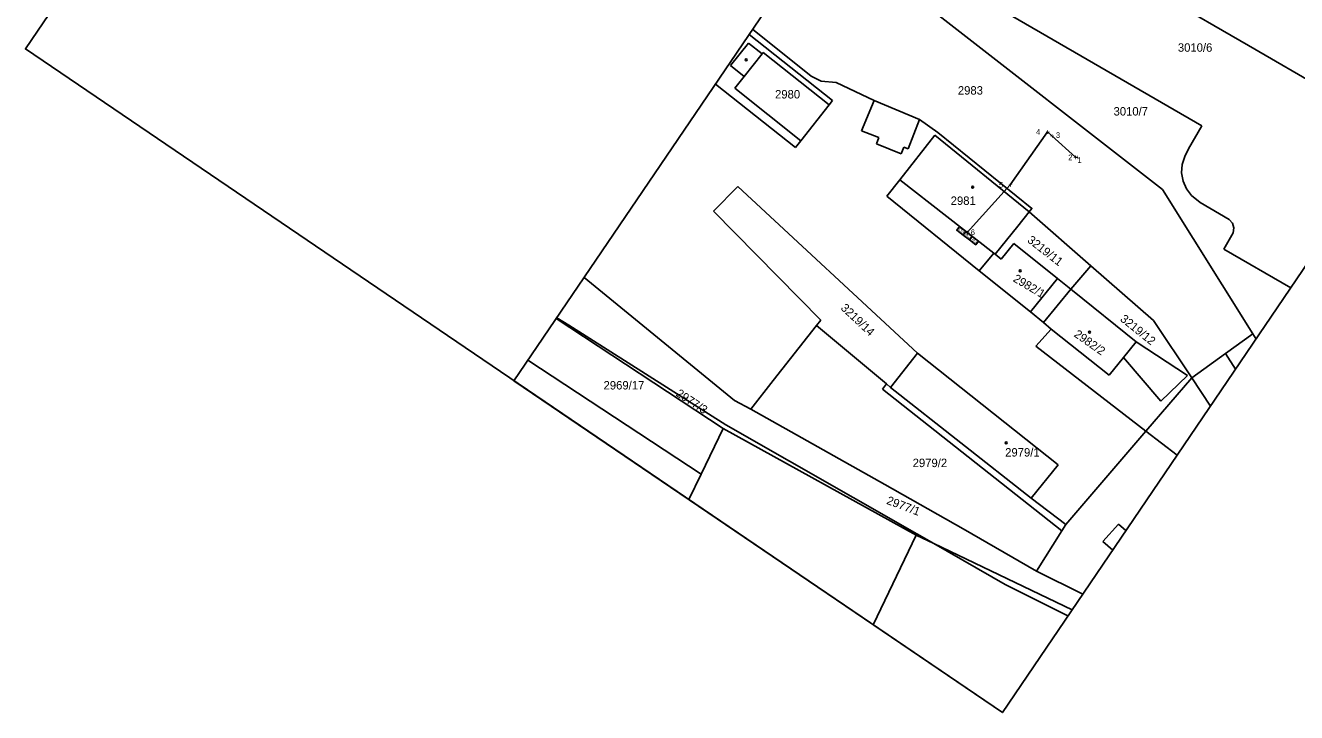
# Model space of a CAD drawing. Extents: x -620405 to -620064, y -1122795 to -1122431.
# Drawn here: x -620404.7 to -620178.7, y -1122795 to -1122672.8 of the extents above; entities that cross this region are included whole.
import ezdxf

# ---------------------------------------------------------------- set-up
doc = ezdxf.new("R2010")
doc.units = 0
for name, color, linetype in [('060602_NAPÁJENÍ_NN', 7, 'Continuous'), ('BODY', 7, 'Continuous'), ('BODY POPIS', 7, 'Continuous'), ('RÁMY', 7, 'Continuous'), ('Vrstva 53', 7, 'Continuous'), ('Vrstva 55', 7, 'Continuous'), ('Vrstva 56', 7, 'Continuous'), ('Vrstva 57', 7, 'Continuous')]:
    doc.layers.add(name, color=color, linetype=linetype)

msp = doc.modelspace()

# ---------------------------------------------------------------- linework, layer by layer
at = {"layer": '060602_NAPÁJENÍ_NN'}
msp.add_lwpolyline([(-620217.64, -1122696.26), (-620218.03, -1122696.24), (-620222.2, -1122692.45), (-620223, -1122691.74), (-620229.59, -1122701.13), (-620237.27, -1122709.63)], dxfattribs=at)
for points in [[(-620238.65, -1122708.58), (-620237.51, -1122709.45), (-620237.99, -1122710.08), (-620239.13, -1122709.21)], [(-620237.51, -1122709.45), (-620236.38, -1122710.32), (-620236.86, -1122710.94), (-620237.99, -1122710.08)], [(-620236.38, -1122710.32), (-620235.25, -1122711.18), (-620235.73, -1122711.81), (-620236.86, -1122710.94)]]:
    msp.add_lwpolyline(points, close=True, dxfattribs=at)
at = {"layer": 'RÁMY'}
for points in [[(-620321.29, -1122554.15), (-620147.57, -1122672.13), (-620231, -1122794.98), (-620404.73, -1122676.99)], [(-620234.43, -1122613.14), (-620147.57, -1122672.13), (-620231, -1122794.98), (-620317.86, -1122735.99)]]:
    msp.add_lwpolyline(points, close=True, dxfattribs=at)
at = {"layer": 'Vrstva 53'}
for p, q in [((-620276.05, -1122674.41), (-620261.22, -1122686.17)), ((-620275.41, -1122673.47), (-620265, -1122681.82)), ((-620265, -1122681.82), (-620263.22, -1122682.69)), ((-620267.81, -1122694.49), (-620282.04, -1122683.25)), ((-620263.22, -1122682.69), (-620260.55, -1122682.94)), ((-620260.55, -1122682.94), (-620253.83, -1122686.12)), ((-620261.82, -1122686.93), (-620261.22, -1122686.17)), ((-620253.83, -1122686.12), (-620245.73, -1122689.53)), ((-620261.82, -1122686.93), (-620266.86, -1122693.31)), ((-620245.73, -1122689.53), (-620242.51, -1122691.82)), ((-620249.26, -1122700.23), (-620243.01, -1122692.32)), ((-620226.24, -1122705.93), (-620243.01, -1122692.32)), ((-620267.81, -1122694.49), (-620266.86, -1122693.31)), ((-620278.07, -1122701.42), (-620282.38, -1122705.84)), ((-620278.07, -1122701.42), (-620246.12, -1122731.05)), ((-620251.53, -1122703.16), (-620249.26, -1122700.23)), ((-620235.14, -1122716.41), (-620251.53, -1122703.16)), ((-620263.28, -1122725.23), (-620282.38, -1122705.84)), ((-620226.24, -1122705.93), (-620228.28, -1122708.48)), ((-620226.24, -1122705.93), (-620215.29, -1122715.52)), ((-620228.28, -1122708.48), (-620232.27, -1122713.47)), ((-620232.51, -1122713.28), (-620235.14, -1122716.41)), ((-620232.27, -1122713.47), (-620232.51, -1122713.28)), ((-620232.27, -1122713.47), (-620231.2, -1122714.35)), ((-620231.2, -1122714.35), (-620228.95, -1122711.56)), ((-620228.95, -1122711.56), (-620221.19, -1122717.82)), ((-620218.86, -1122719.7), (-620215.29, -1122715.52)), ((-620278.65, -1122739.48), (-620305.39, -1122717.62)), ((-620226.02, -1122723.74), (-620235.14, -1122716.41)), ((-620221.19, -1122717.82), (-620218.86, -1122719.7)), ((-620218.86, -1122719.7), (-620223.68, -1122725.62)), ((-620226.02, -1122723.74), (-620223.68, -1122725.62)), ((-620271.78, -1122735.94), (-620264.06, -1122726.18)), ((-620263.28, -1122725.23), (-620264.06, -1122726.18)), ((-620251.62, -1122736.54), (-620264.06, -1122726.18)), ((-620222.3, -1122726.83), (-620225.04, -1122729.85)), ((-620223.68, -1122725.62), (-620222.3, -1122726.83)), ((-620250.89, -1122737.15), (-620246.12, -1122731.05)), ((-620246.12, -1122731.05), (-620221.1, -1122750.9)), ((-620225.04, -1122729.85), (-620205.48, -1122744.93)), ((-620275.74, -1122741.01), (-620271.78, -1122735.94)), ((-620205.48, -1122744.93), (-620197.33, -1122735.44)), ((-620197.33, -1122735.44), (-620193.99, -1122740.48)), ((-620252.35, -1122737.47), (-620251.62, -1122736.54)), ((-620220.43, -1122762.64), (-620252.35, -1122737.47)), ((-620250.89, -1122737.15), (-620251.62, -1122736.54)), ((-620278.65, -1122739.48), (-620275.74, -1122741.01)), ((-620251.9, -1122754.44), (-620275.74, -1122741.01)), ((-620205.48, -1122744.93), (-620219.74, -1122761.53)), ((-620221.1, -1122750.9), (-620225.88, -1122756.88)), ((-620238, -1122762.33), (-620251.9, -1122754.44)), ((-620225.88, -1122756.88), (-620219.74, -1122761.53)), ((-620224.92, -1122769.84), (-620238, -1122762.33)), ((-620220.43, -1122762.64), (-620224.92, -1122769.84)), ((-620219.74, -1122761.53), (-620220.43, -1122762.64)), ((-620213.13, -1122764.54), (-620210.34, -1122761.46)), ((-620210.34, -1122761.46), (-620209.04, -1122762.63)), ((-620211.39, -1122766.1), (-620213.13, -1122764.54)), ((-620216.7, -1122773.93), (-620224.92, -1122769.84))]:
    msp.add_line(p, q, dxfattribs=at)
msp.add_lwpolyline([(-620242.51, -1122691.82), (-620225.75, -1122705.35), (-620226.24, -1122705.93)], dxfattribs=at)
at = {"layer": 'Vrstva 55'}
for p, q in [((-620187.21, -1122676.39), (-620251.94, -1122638.92)), ((-620261.22, -1122652.59), (-620195.53, -1122690.65)), ((-620243.36, -1122670.23), (-620202.54, -1122702)), ((-620261.22, -1122686.17), (-620276.05, -1122674.41)), ((-620265, -1122681.82), (-620275.41, -1122673.47)), ((-620187.21, -1122676.39), (-620163.01, -1122690.49)), ((-620265, -1122681.82), (-620263.22, -1122682.69)), ((-620282.04, -1122683.25), (-620267.81, -1122694.49)), ((-620263.22, -1122682.69), (-620260.55, -1122682.94)), ((-620260.55, -1122682.94), (-620253.83, -1122686.12)), ((-620261.82, -1122686.93), (-620261.22, -1122686.17)), ((-620253.83, -1122686.12), (-620245.73, -1122689.53)), ((-620266.86, -1122693.31), (-620261.82, -1122686.93)), ((-620245.73, -1122689.53), (-620242.51, -1122691.82)), ((-620197.92, -1122694.75), (-620195.53, -1122690.65)), ((-620249.26, -1122700.23), (-620243.01, -1122692.32)), ((-620243.01, -1122692.32), (-620226.24, -1122705.93)), ((-620225.75, -1122705.35), (-620242.51, -1122691.82)), ((-620267.81, -1122694.49), (-620266.86, -1122693.31)), ((-620198.58, -1122696.08), (-620197.92, -1122694.75)), ((-620199.13, -1122698.99), (-620199.01, -1122697.5)), ((-620199.01, -1122697.5), (-620198.58, -1122696.08)), ((-620198.88, -1122700.47), (-620199.13, -1122698.99)), ((-620278.07, -1122701.42), (-620282.38, -1122705.84)), ((-620246.12, -1122731.05), (-620278.07, -1122701.42)), ((-620251.53, -1122703.16), (-620249.26, -1122700.23)), ((-620202.54, -1122702), (-620186.47, -1122727.64)), ((-620198.25, -1122701.83), (-620198.88, -1122700.47)), ((-620197.37, -1122703.03), (-620198.25, -1122701.83)), ((-620235.14, -1122716.41), (-620251.53, -1122703.16)), ((-620195.84, -1122704.31), (-620197.37, -1122703.03)), ((-620190.67, -1122707.32), (-620195.84, -1122704.31)), ((-620282.38, -1122705.84), (-620263.28, -1122725.23)), ((-620226.24, -1122705.93), (-620228.28, -1122708.48)), ((-620225.75, -1122705.35), (-620226.24, -1122705.93)), ((-620215.29, -1122715.52), (-620226.24, -1122705.93)), ((-620228.28, -1122708.48), (-620232.27, -1122713.47)), ((-620190.09, -1122707.94), (-620190.67, -1122707.32)), ((-620189.82, -1122708.78), (-620190.09, -1122707.94)), ((-620189.94, -1122709.65), (-620189.82, -1122708.78)), ((-620191.6, -1122712.59), (-620189.94, -1122709.65)), ((-620232.51, -1122713.28), (-620235.14, -1122716.41)), ((-620232.27, -1122713.47), (-620232.51, -1122713.28)), ((-620232.27, -1122713.47), (-620231.2, -1122714.35)), ((-620231.2, -1122714.35), (-620228.95, -1122711.56)), ((-620228.95, -1122711.56), (-620221.19, -1122717.82)), ((-620179.71, -1122719.46), (-620191.6, -1122712.59)), ((-620218.86, -1122719.7), (-620215.29, -1122715.52)), ((-620204.16, -1122725.27), (-620215.29, -1122715.52)), ((-620305.39, -1122717.62), (-620278.65, -1122739.48)), ((-620235.14, -1122716.41), (-620226.02, -1122723.74)), ((-620221.19, -1122717.82), (-620218.86, -1122719.7)), ((-620223.68, -1122725.62), (-620218.86, -1122719.7)), ((-620218.86, -1122719.7), (-620218.55, -1122719.95)), ((-620218.55, -1122719.95), (-620207.24, -1122729.07)), ((-620308.1, -1122726.09), (-620310.25, -1122724.77)), ((-620226.02, -1122723.74), (-620223.68, -1122725.62)), ((-620310.36, -1122724.93), (-620280.66, -1122744.45)), ((-620280.18, -1122743.84), (-620308.1, -1122726.09)), ((-620271.78, -1122735.94), (-620264.06, -1122726.18)), ((-620263.28, -1122725.23), (-620264.06, -1122726.18)), ((-620251.62, -1122736.54), (-620264.06, -1122726.18)), ((-620222.3, -1122726.83), (-620225.04, -1122729.85)), ((-620223.68, -1122725.62), (-620222.3, -1122726.83)), ((-620222.3, -1122726.83), (-620212.02, -1122735)), ((-620197.33, -1122735.44), (-620204.16, -1122725.27)), ((-620198.09, -1122735.05), (-620207.24, -1122729.07)), ((-620186.47, -1122727.64), (-620191.31, -1122731.11)), ((-620186.47, -1122727.64), (-620185.89, -1122728.56)), ((-620250.89, -1122737.15), (-620246.12, -1122731.05)), ((-620246.12, -1122731.05), (-620221.1, -1122750.9)), ((-620225.04, -1122729.85), (-620205.48, -1122744.93)), ((-620191.31, -1122731.11), (-620197.33, -1122735.44)), ((-620315.36, -1122732.3), (-620284.57, -1122752.56)), ((-620212.02, -1122735), (-620209.48, -1122731.85)), ((-620209.48, -1122731.85), (-620202.82, -1122739.59)), ((-620275.74, -1122741.01), (-620271.78, -1122735.94)), ((-620205.48, -1122744.93), (-620197.33, -1122735.44)), ((-620202.82, -1122739.59), (-620198.09, -1122735.05)), ((-620193.99, -1122740.48), (-620197.33, -1122735.44)), ((-620252.35, -1122737.47), (-620251.62, -1122736.54)), ((-620220.43, -1122762.64), (-620252.35, -1122737.47)), ((-620250.89, -1122737.15), (-620251.62, -1122736.54)), ((-620278.65, -1122739.48), (-620275.74, -1122741.01)), ((-620275.74, -1122741.01), (-620251.9, -1122754.44)), ((-620280.66, -1122744.45), (-620284.57, -1122752.56)), ((-620280.66, -1122744.45), (-620246.32, -1122763.41)), ((-620280.18, -1122743.84), (-620246.23, -1122763.17)), ((-620205.48, -1122744.93), (-620219.74, -1122761.53)), ((-620221.1, -1122750.9), (-620225.88, -1122756.88)), ((-620284.57, -1122752.56), (-620286.76, -1122757.11)), ((-620251.9, -1122754.44), (-620238, -1122762.33)), ((-620225.88, -1122756.88), (-620219.74, -1122761.53)), ((-620246.23, -1122763.17), (-620243.2, -1122764.91)), ((-620238, -1122762.33), (-620224.92, -1122769.84)), ((-620220.43, -1122762.64), (-620224.92, -1122769.84)), ((-620219.74, -1122761.53), (-620220.43, -1122762.64)), ((-620213.13, -1122764.54), (-620210.34, -1122761.46)), ((-620210.34, -1122761.46), (-620209.04, -1122762.63)), ((-620246.32, -1122763.41), (-620253.99, -1122779.36)), ((-620246.32, -1122763.41), (-620243.2, -1122764.91)), ((-620243.2, -1122764.91), (-620230.53, -1122772.18)), ((-620243.2, -1122764.91), (-620218.61, -1122776.73)), ((-620211.39, -1122766.1), (-620213.13, -1122764.54)), ((-620224.92, -1122769.84), (-620216.7, -1122773.93)), ((-620219.74, -1122777.62), (-620230.53, -1122772.18)), ((-620219.34, -1122777.8), (-620219.74, -1122777.62))]:
    msp.add_line(p, q, dxfattribs=at)
at = {"layer": 'Vrstva 56'}
for p, q in [((-620279.35, -1122679.94), (-620276.17, -1122675.94)), ((-620276.17, -1122675.94), (-620273.73, -1122677.87)), ((-620276.91, -1122681.88), (-620273.73, -1122677.87)), ((-620273.73, -1122677.87), (-620273.55, -1122677.64)), ((-620273.55, -1122677.64), (-620261.82, -1122686.93)), ((-620276.91, -1122681.88), (-620279.35, -1122679.94)), ((-620278.56, -1122683.97), (-620276.91, -1122681.88)), ((-620266.86, -1122693.31), (-620278.56, -1122683.97)), ((-620253.83, -1122686.12), (-620256.06, -1122691.57)), ((-620245.73, -1122689.53), (-620247.73, -1122694.76)), ((-620256.06, -1122691.57), (-620252.97, -1122692.73)), ((-620252.97, -1122692.73), (-620253.4, -1122693.88)), ((-620253.4, -1122693.88), (-620248.99, -1122695.65)), ((-620248.99, -1122695.65), (-620248.5, -1122694.45)), ((-620248.5, -1122694.45), (-620247.73, -1122694.76)), ((-620249.26, -1122700.23), (-620232.51, -1122713.28)), ((-620226.02, -1122723.74), (-620221.19, -1122717.82)), ((-620209.48, -1122731.85), (-620207.24, -1122729.07)), ((-620191.31, -1122731.11), (-620189.53, -1122733.92)), ((-620225.88, -1122756.88), (-620250.89, -1122737.15)), ((-620205.48, -1122744.93), (-620199.92, -1122749.21))]:
    msp.add_line(p, q, dxfattribs=at)
at = {"layer": 'Vrstva 57'}
for centre in [(-620276.54, -1122678.91), (-620236.29, -1122701.58), (-620227.84, -1122716.43), (-620215.5, -1122727.32), (-620230.31, -1122747.04)]:
    msp.add_circle(centre, 0.175, dxfattribs=at)

# ---------------------------------------------------------------- texts
at = {"layer": '060602_NAPÁJENÍ_NN'}
for s, p in [('KS1', (-620238.96, -1122709.1)), ('RE2', (-620237.87, -1122709.93)), ('RE1', (-620236.71, -1122710.82))]:
    msp.add_text(s, height=0.5, rotation=322.5799, dxfattribs=at).set_placement(p)
at = {"layer": 'BODY'}
for p in [(-620223.33, -1122692.24), (-620222.53, -1122692.95), (-620218.37, -1122696.74), (-620217.98, -1122696.76), (-620229.93, -1122701.63), (-620237.61, -1122710.13)]:
    msp.add_text('+', height=1, dxfattribs=at).set_placement(p)
at = {"layer": 'BODY POPIS'}
for s, p in [('4', (-620225.01, -1122692.23)), ('3', (-620221.49, -1122692.81)), ('2', (-620219.29, -1122696.76)), ('1', (-620217.64, -1122697.26)), ('5', (-620231.61, -1122701.62)), ('6', (-620236.63, -1122710.07))]:
    msp.add_text(s, height=1, dxfattribs=at).set_placement(p)
at = {"layer": 'Vrstva 57'}
for s, p in [('3010/6', (-620199.8, -1122677.48)), ('2983', (-620238.92, -1122685.1)), ('2980', (-620271.43, -1122685.79)), ('3010/7', (-620211.24, -1122688.82)), ('2981', (-620240.2, -1122704.71)), ('2969/17', (-620301.92, -1122737.53)), ('2979/1', (-620230.51, -1122749.46)), ('2979/2', (-620246.96, -1122751.33))]:
    msp.add_text(s, height=1.5, dxfattribs=at).set_placement(p)
for s, rotation, p in [('3219/11', 322.1138, (-620226.69, -1122711.22)), ('2982/1', 329.4, (-620229.23, -1122718.23)), ('3219/14', 316.8, (-620259.86, -1122723.19)), ('3219/12', 321.2409, (-620210.18, -1122725.22)), ('2982/2', 324.9, (-620218.4, -1122728.01)), ('2977/3', 326.397, (-620289.18, -1122738.58)), ('2977/1', 339.3, (-620251.72, -1122757.84))]:
    msp.add_text(s, height=1.5, rotation=rotation, dxfattribs=at).set_placement(p)

doc.saveas('drawing.dxf')
